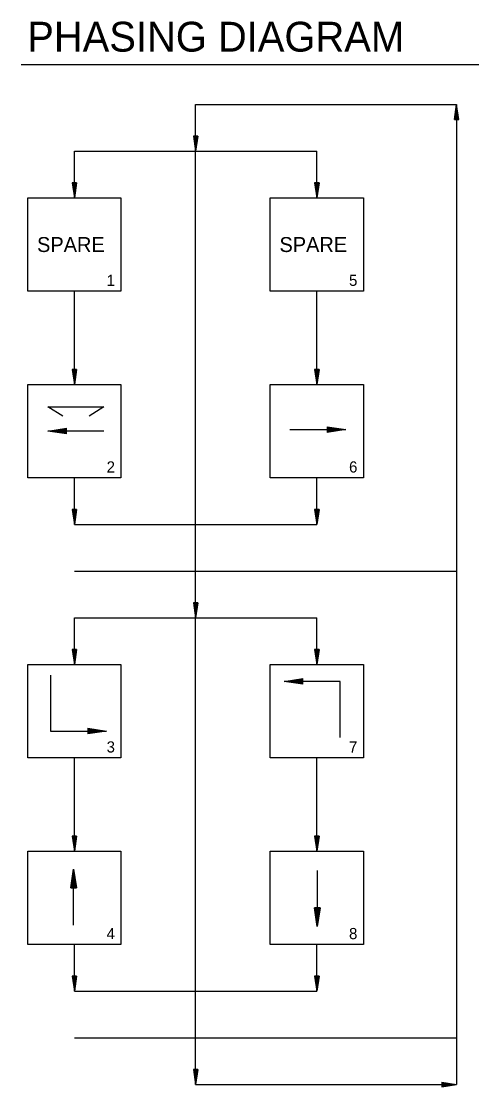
# Model space of a CAD drawing. Extents: x 110 to 419214, y -565865 to 630.
# Drawn here: x 110.2 to 232.8, y 197.1 to 482.5 of the extents above; entities that cross this region are included whole.
import ezdxf

# ---------------------------------------------------------------- set-up
doc = ezdxf.new("R2010")
doc.units = 0
for name, color, linetype in [('R_Draft', 7, 'Continuous'), ('T_Drafting', 7, 'Continuous'), ('T_Notes', 7, 'Continuous')]:
    doc.layers.add(name, color=color, linetype=linetype)

msp = doc.modelspace()

# ---------------------------------------------------------------- linework, layer by layer
at = {"layer": 'R_Draft'}
for p, q in [((226.3, 456.21), (226.9, 460.21)), ((226.4, 456.21), (226.9, 459.54)), ((227.5, 456.21), (226.9, 460.21)), ((227.4, 456.21), (226.9, 459.54)), ((226.5, 456.21), (226.9, 458.85)), ((226.6, 456.21), (226.9, 458.19)), ((226.7, 456.21), (226.9, 457.51)), ((226.8, 456.21), (226.9, 456.84)), ((227.29, 456.21), (226.9, 458.85)), ((227.19, 456.21), (226.9, 458.19)), ((227.09, 456.21), (226.9, 457.51)), ((226.99, 456.21), (226.9, 456.84)), ((226.3, 456.21), (227.5, 456.21)), ((156.3, 451.71), (156.9, 447.71)), ((157.5, 451.71), (156.3, 451.71)), ((156.4, 451.71), (156.9, 448.38)), ((156.5, 451.71), (156.9, 449.07)), ((156.6, 451.71), (156.9, 449.73)), ((156.7, 451.71), (156.9, 450.41)), ((156.8, 451.71), (156.9, 451.08)), ((157.5, 451.71), (156.9, 447.71)), ((157.09, 451.71), (156.9, 450.41)), ((157.29, 451.71), (156.9, 449.07)), ((157.4, 451.71), (156.9, 448.38)), ((157.19, 451.71), (156.9, 449.73)), ((156.99, 451.71), (156.9, 451.08)), ((123.8, 439.21), (124.4, 435.21)), ((125, 439.21), (123.8, 439.21)), ((123.9, 439.21), (124.4, 435.88)), ((124, 439.21), (124.4, 436.57)), ((124.1, 439.21), (124.4, 437.23)), ((124.2, 439.21), (124.4, 437.91)), ((124.3, 439.21), (124.4, 438.58)), ((125, 439.21), (124.4, 435.21)), ((124.59, 439.21), (124.4, 437.91)), ((124.79, 439.21), (124.4, 436.57)), ((124.9, 439.21), (124.4, 435.88)), ((124.69, 439.21), (124.4, 437.23)), ((124.49, 439.21), (124.4, 438.58)), ((188.8, 439.21), (189.4, 435.21)), ((190, 439.21), (188.8, 439.21)), ((188.9, 439.21), (189.4, 435.88)), ((189, 439.21), (189.4, 436.57)), ((189.1, 439.21), (189.4, 437.23)), ((189.2, 439.21), (189.4, 437.91)), ((189.3, 439.21), (189.4, 438.58)), ((190, 439.21), (189.4, 435.21)), ((189.59, 439.21), (189.4, 437.91)), ((189.79, 439.21), (189.4, 436.57)), ((189.9, 439.21), (189.4, 435.88)), ((189.69, 439.21), (189.4, 437.23)), ((189.49, 439.21), (189.4, 438.58)), ((123.8, 389.21), (124.4, 385.21)), ((125, 389.21), (123.8, 389.21)), ((123.9, 389.21), (124.4, 385.88)), ((124, 389.21), (124.4, 386.57)), ((124.1, 389.21), (124.4, 387.23)), ((124.2, 389.21), (124.4, 387.91)), ((124.3, 389.21), (124.4, 388.58)), ((125, 389.21), (124.4, 385.21)), ((124.59, 389.21), (124.4, 387.91)), ((124.79, 389.21), (124.4, 386.57)), ((124.9, 389.21), (124.4, 385.88)), ((124.69, 389.21), (124.4, 387.23)), ((124.49, 389.21), (124.4, 388.58)), ((188.8, 389.21), (189.4, 385.21)), ((190, 389.21), (188.8, 389.21)), ((188.9, 389.21), (189.4, 385.88)), ((189, 389.21), (189.4, 386.57)), ((189.1, 389.21), (189.4, 387.23)), ((189.2, 389.21), (189.4, 387.91)), ((189.3, 389.21), (189.4, 388.58)), ((190, 389.21), (189.4, 385.21)), ((189.59, 389.21), (189.4, 387.91)), ((189.79, 389.21), (189.4, 386.57)), ((189.9, 389.21), (189.4, 385.88)), ((189.69, 389.21), (189.4, 387.23)), ((189.49, 389.21), (189.4, 388.58)), ((123.8, 351.71), (124.4, 347.71)), ((125, 351.71), (123.8, 351.71)), ((123.9, 351.71), (124.4, 348.38)), ((124, 351.71), (124.4, 349.07)), ((124.1, 351.71), (124.4, 349.73)), ((124.2, 351.71), (124.4, 350.41)), ((124.3, 351.71), (124.4, 351.08)), ((125, 351.71), (124.4, 347.71)), ((124.59, 351.71), (124.4, 350.41)), ((124.79, 351.71), (124.4, 349.07)), ((124.9, 351.71), (124.4, 348.38)), ((124.69, 351.71), (124.4, 349.73)), ((124.49, 351.71), (124.4, 351.08)), ((188.8, 351.71), (189.4, 347.71)), ((190, 351.71), (188.8, 351.71)), ((188.9, 351.71), (189.4, 348.38)), ((189, 351.71), (189.4, 349.07)), ((189.1, 351.71), (189.4, 349.73)), ((189.2, 351.71), (189.4, 350.41)), ((189.3, 351.71), (189.4, 351.08)), ((190, 351.71), (189.4, 347.71)), ((189.59, 351.71), (189.4, 350.41)), ((189.79, 351.71), (189.4, 349.07)), ((189.9, 351.71), (189.4, 348.38)), ((189.69, 351.71), (189.4, 349.73)), ((189.49, 351.71), (189.4, 351.08)), ((156.3, 326.71), (156.9, 322.71)), ((157.5, 326.71), (156.3, 326.71)), ((156.4, 326.71), (156.9, 323.38)), ((156.5, 326.71), (156.9, 324.07)), ((156.6, 326.71), (156.9, 324.73)), ((156.7, 326.71), (156.9, 325.41)), ((156.8, 326.71), (156.9, 326.08)), ((157.5, 326.71), (156.9, 322.71)), ((157.09, 326.71), (156.9, 325.41)), ((157.29, 326.71), (156.9, 324.07)), ((157.4, 326.71), (156.9, 323.38)), ((157.19, 326.71), (156.9, 324.73)), ((156.99, 326.71), (156.9, 326.08)), ((123.8, 314.21), (124.4, 310.21)), ((125, 314.21), (123.8, 314.21)), ((123.9, 314.21), (124.4, 310.88)), ((124, 314.21), (124.4, 311.57)), ((124.1, 314.21), (124.4, 312.23)), ((124.2, 314.21), (124.4, 312.91)), ((124.3, 314.21), (124.4, 313.58)), ((125, 314.21), (124.4, 310.21)), ((124.59, 314.21), (124.4, 312.91)), ((124.79, 314.21), (124.4, 311.57)), ((124.9, 314.21), (124.4, 310.88)), ((124.69, 314.21), (124.4, 312.23)), ((124.49, 314.21), (124.4, 313.58)), ((188.8, 314.21), (189.4, 310.21)), ((190, 314.21), (188.8, 314.21)), ((188.9, 314.21), (189.4, 310.88)), ((189, 314.21), (189.4, 311.57)), ((189.1, 314.21), (189.4, 312.23)), ((189.2, 314.21), (189.4, 312.91)), ((189.3, 314.21), (189.4, 313.58)), ((190, 314.21), (189.4, 310.21)), ((189.59, 314.21), (189.4, 312.91)), ((189.79, 314.21), (189.4, 311.57)), ((189.9, 314.21), (189.4, 310.88)), ((189.69, 314.21), (189.4, 312.23)), ((189.49, 314.21), (189.4, 313.58)), ((123.8, 264.21), (124.4, 260.21)), ((125, 264.21), (123.8, 264.21)), ((123.9, 264.21), (124.4, 260.88)), ((124, 264.21), (124.4, 261.57)), ((124.1, 264.21), (124.4, 262.23)), ((124.2, 264.21), (124.4, 262.91)), ((124.3, 264.21), (124.4, 263.58)), ((125, 264.21), (124.4, 260.21)), ((124.59, 264.21), (124.4, 262.91)), ((124.79, 264.21), (124.4, 261.57)), ((124.9, 264.21), (124.4, 260.88)), ((124.69, 264.21), (124.4, 262.23)), ((124.49, 264.21), (124.4, 263.58)), ((188.8, 264.21), (189.4, 260.21)), ((190, 264.21), (188.8, 264.21)), ((188.9, 264.21), (189.4, 260.88)), ((189, 264.21), (189.4, 261.57)), ((189.1, 264.21), (189.4, 262.23)), ((189.2, 264.21), (189.4, 262.91)), ((189.3, 264.21), (189.4, 263.58)), ((190, 264.21), (189.4, 260.21)), ((189.59, 264.21), (189.4, 262.91)), ((189.79, 264.21), (189.4, 261.57)), ((189.9, 264.21), (189.4, 260.88)), ((189.69, 264.21), (189.4, 262.23)), ((189.49, 264.21), (189.4, 263.58)), ((123.8, 226.71), (124.4, 222.71)), ((125, 226.71), (123.8, 226.71)), ((123.9, 226.71), (124.4, 223.38)), ((124, 226.71), (124.4, 224.07)), ((124.1, 226.71), (124.4, 224.73)), ((124.2, 226.71), (124.4, 225.41)), ((124.3, 226.71), (124.4, 226.08)), ((125, 226.71), (124.4, 222.71)), ((124.59, 226.71), (124.4, 225.41)), ((124.79, 226.71), (124.4, 224.07)), ((124.9, 226.71), (124.4, 223.38)), ((124.69, 226.71), (124.4, 224.73)), ((124.49, 226.71), (124.4, 226.08)), ((188.8, 226.71), (189.4, 222.71)), ((190, 226.71), (188.8, 226.71)), ((188.9, 226.71), (189.4, 223.38)), ((189, 226.71), (189.4, 224.07)), ((189.1, 226.71), (189.4, 224.73)), ((189.2, 226.71), (189.4, 225.41)), ((189.3, 226.71), (189.4, 226.08)), ((190, 226.71), (189.4, 222.71)), ((189.59, 226.71), (189.4, 225.41)), ((189.79, 226.71), (189.4, 224.07)), ((189.9, 226.71), (189.4, 223.38)), ((189.69, 226.71), (189.4, 224.73)), ((189.49, 226.71), (189.4, 226.08)), ((156.3, 201.71), (156.9, 197.71)), ((157.5, 201.71), (156.3, 201.71)), ((156.4, 201.71), (156.9, 198.38)), ((156.5, 201.71), (156.9, 199.07)), ((156.6, 201.71), (156.9, 199.73)), ((156.7, 201.71), (156.9, 200.41)), ((156.8, 201.71), (156.9, 201.08)), ((157.5, 201.71), (156.9, 197.71)), ((157.09, 201.71), (156.9, 200.41)), ((157.29, 201.71), (156.9, 199.07)), ((157.4, 201.71), (156.9, 198.38)), ((157.19, 201.71), (156.9, 199.73)), ((156.99, 201.71), (156.9, 201.08)), ((222.9, 198.31), (226.9, 197.71)), ((222.9, 198.31), (222.9, 197.11)), ((222.9, 198.21), (226.23, 197.71)), ((222.9, 198.11), (225.54, 197.71)), ((222.9, 198.01), (224.87, 197.71)), ((222.9, 197.9), (224.2, 197.71)), ((222.9, 197.8), (223.53, 197.71)), ((222.9, 197.11), (226.9, 197.71)), ((222.9, 197.51), (224.2, 197.71)), ((222.9, 197.31), (225.54, 197.71)), ((222.9, 197.21), (226.23, 197.71)), ((222.9, 197.41), (224.87, 197.71)), ((222.9, 197.62), (223.53, 197.71))]:
    msp.add_line(p, q, dxfattribs=at)
at = {"layer": 'T_Drafting'}
for p, q in [((156.9, 197.71), (156.9, 460.21)), ((156.9, 460.21), (226.9, 460.21)), ((226.9, 460.21), (226.9, 197.71)), ((124.4, 435.21), (124.4, 447.71)), ((124.4, 447.71), (189.4, 447.71)), ((189.4, 435.21), (189.4, 447.71)), ((124.4, 385.21), (124.4, 410.21)), ((189.4, 385.21), (189.4, 410.21)), ((192.19, 373.89), (197.19, 373.14)), ((192.19, 373.89), (192.19, 372.39)), ((117.33, 372.76), (122.33, 373.51)), ((132.33, 372.76), (117.33, 372.76)), ((122.33, 372.01), (117.33, 372.76)), ((122.33, 373.39), (118.16, 372.76)), ((118.16, 372.76), (122.33, 372.14)), ((119.02, 372.76), (122.33, 373.26)), ((122.33, 372.26), (119.02, 372.76)), ((122.33, 373.13), (119.85, 372.76)), ((119.85, 372.76), (122.33, 372.39)), ((120.7, 372.76), (122.33, 373.01)), ((122.33, 372.52), (120.7, 372.76)), ((122.33, 372.88), (121.54, 372.76)), ((121.54, 372.76), (122.33, 372.64)), ((122.33, 372.01), (122.33, 373.51)), ((182.19, 373.14), (197.19, 373.14)), ((196.35, 373.14), (192.19, 373.77)), ((192.19, 373.64), (195.49, 373.14)), ((194.66, 373.14), (192.19, 373.51)), ((192.19, 373.38), (193.81, 373.14)), ((192.98, 373.14), (192.19, 373.26)), ((197.19, 373.14), (192.19, 372.39)), ((192.19, 372.52), (196.35, 373.14)), ((195.49, 373.14), (192.19, 372.64)), ((192.19, 372.77), (194.66, 373.14)), ((193.81, 373.14), (192.19, 372.9)), ((192.19, 373.02), (192.98, 373.14)), ((124.4, 347.71), (124.4, 360.21)), ((189.4, 347.71), (189.4, 360.21)), ((124.4, 347.71), (189.4, 347.71)), ((124.4, 335.21), (226.9, 335.21)), ((124.4, 322.71), (189.4, 322.71)), ((124.4, 310.21), (124.4, 322.71)), ((189.4, 310.21), (189.4, 322.71)), ((118, 307.39), (118, 292.39)), ((180.64, 305.68), (185.64, 306.43)), ((195.64, 305.68), (180.64, 305.68)), ((185.64, 304.93), (180.64, 305.68)), ((185.64, 306.3), (181.47, 305.68)), ((181.47, 305.68), (185.64, 305.05)), ((182.33, 305.68), (185.64, 306.18)), ((185.64, 305.18), (182.33, 305.68)), ((185.64, 306.05), (183.17, 305.68)), ((183.17, 305.68), (185.64, 305.31)), ((184.01, 305.68), (185.64, 305.92)), ((185.64, 305.44), (184.01, 305.68)), ((185.64, 305.8), (184.85, 305.68)), ((184.85, 305.68), (185.64, 305.56)), ((185.64, 304.93), (185.64, 306.43)), ((195.64, 290.68), (195.64, 305.68)), ((118, 292.39), (133, 292.39)), ((128, 293.14), (133, 292.39)), ((128, 293.14), (128, 291.64)), ((132.17, 292.39), (128, 293.01)), ((128, 292.89), (131.31, 292.39)), ((130.47, 292.39), (128, 292.76)), ((128, 292.63), (129.63, 292.39)), ((128.79, 292.39), (128, 292.51)), ((133, 292.39), (128, 291.64)), ((128, 291.76), (132.17, 292.39)), ((131.31, 292.39), (128, 291.89)), ((128, 292.02), (130.47, 292.39)), ((129.63, 292.39), (128, 292.14)), ((128, 292.27), (128.79, 292.39)), ((124.4, 260.21), (124.4, 285.21)), ((189.4, 260.21), (189.4, 285.21)), ((123.43, 250.35), (124.18, 255.35)), ((124.18, 254.51), (123.55, 250.35)), ((124.18, 240.35), (124.18, 255.35)), ((124.18, 255.35), (124.93, 250.35)), ((124.8, 250.35), (124.18, 254.51)), ((189.52, 255), (189.52, 240)), ((123.68, 250.35), (124.18, 253.65)), ((124.18, 252.82), (123.8, 250.35)), ((123.93, 250.35), (124.18, 251.97)), ((124.18, 253.65), (124.67, 250.35)), ((124.55, 250.35), (124.18, 252.82)), ((124.18, 251.97), (124.42, 250.35)), ((123.43, 250.35), (124.93, 250.35)), ((124.18, 251.14), (124.06, 250.35)), ((124.29, 250.35), (124.18, 251.14)), ((189.52, 240), (188.77, 245)), ((190.27, 245), (188.77, 245)), ((188.89, 245), (189.52, 240.83)), ((189.52, 241.69), (189.02, 245)), ((189.15, 245), (189.52, 242.53)), ((189.52, 243.37), (189.27, 245)), ((189.4, 245), (189.52, 244.21)), ((189.52, 244.21), (189.64, 245)), ((189.76, 245), (189.52, 243.37)), ((189.52, 242.53), (189.89, 245)), ((190.02, 245), (189.52, 241.69)), ((189.52, 240.83), (190.14, 245)), ((190.27, 245), (189.52, 240)), ((124.4, 222.71), (124.4, 235.21)), ((189.4, 222.71), (189.4, 235.21)), ((124.4, 222.71), (189.4, 222.71)), ((124.4, 210.21), (226.9, 210.21)), ((156.9, 197.71), (226.9, 197.71))]:
    msp.add_line(p, q, dxfattribs=at)
for points in [[(111.9, 435.21), (136.9, 435.21), (136.9, 410.21), (111.9, 410.21)], [(176.9, 435.21), (201.9, 435.21), (201.9, 410.21), (176.9, 410.21)], [(111.9, 385.21), (136.9, 385.21), (136.9, 360.21), (111.9, 360.21)], [(176.9, 385.21), (201.9, 385.21), (201.9, 360.21), (176.9, 360.21)], [(111.9, 310.21), (136.9, 310.21), (136.9, 285.21), (111.9, 285.21)], [(176.9, 310.21), (201.9, 310.21), (201.9, 285.21), (176.9, 285.21)], [(111.9, 260.21), (136.9, 260.21), (136.9, 235.21), (111.9, 235.21)], [(176.9, 260.21), (201.9, 260.21), (201.9, 235.21), (176.9, 235.21)]]:
    msp.add_lwpolyline(points, close=True, dxfattribs=at)
msp.add_lwpolyline([(121.33, 376.74), (117.33, 379.24), (132.33, 379.24), (128.33, 376.74)], dxfattribs=at)
at = {"layer": 'T_Notes'}
msp.add_line((110.17, 470.92), (232.82, 470.92), dxfattribs=at)

# ---------------------------------------------------------------- texts
at = {"layer": 'T_Drafting'}
for p in [(114.4, 420.71), (179.4, 420.71)]:
    msp.add_text('SPARE', height=4, rotation=360, dxfattribs=at).set_placement(p)
at = {"layer": 'T_Notes'}
for s, height, p in [('PHASING DIAGRAM', 8, (111.77, 474.39)), ('1', 3, (133.05, 411.63)), ('5', 3, (198.05, 411.63)), ('2', 3, (133.05, 361.63)), ('6', 3, (198.05, 361.63)), ('3', 3, (133.05, 286.63)), ('7', 3, (198.05, 286.63)), ('4', 3, (133.05, 236.63)), ('8', 3, (198.05, 236.63))]:
    msp.add_text(s, height=height, rotation=360, dxfattribs=at).set_placement(p)

doc.saveas('drawing.dxf')
